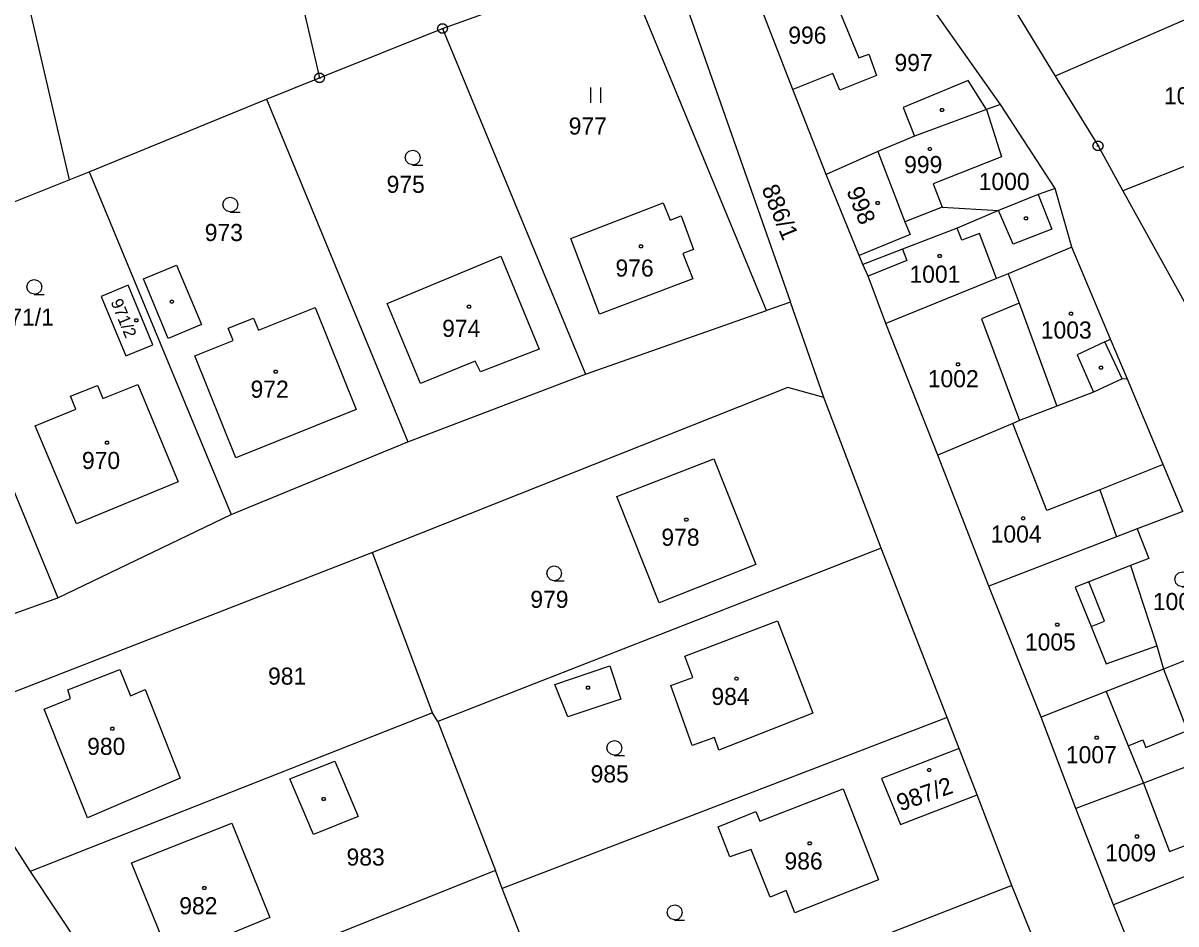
# Model space of a CAD drawing. Extents: x -609861 to -605046, y -1120287 to -1116307.
# Drawn here: x -607750.1 to -607635.6, y -1118647.5 to -1118558 of the extents above; entities that cross this region are included whole.
import ezdxf

# ---------------------------------------------------------------- set-up
doc = ezdxf.new("R2010")
doc.units = 0
for name, color, linetype in [('Vrstva 1', 7, 'Continuous'), ('Vrstva 2', 7, 'Continuous'), ('Vrstva 3', 7, 'Continuous'), ('Vrstva 4', 7, 'Continuous'), ('Vrstva 5', 7, 'Continuous'), ('Vrstva 8', 7, 'Continuous')]:
    doc.layers.add(name, color=color, linetype=linetype)

msp = doc.modelspace()

# ---------------------------------------------------------------- linework, layer by layer
at = {"layer": 'Vrstva 1'}
for p, q in [((-607730.23, -1118522.38), (-607720.65, -1118563.48)), ((-607755.47, -1118530.89), (-607745.51, -1118573.59)), ((-607660.15, -1118542.68), (-607647.55, -1118563.29)), ((-607653, -1118566.11), (-607664.28, -1118550.12)), ((-607708.42, -1118558.58), (-607690.47, -1118552.09)), ((-607676.23, -1118586.6), (-607690.47, -1118552.09)), ((-607670.62, -1118552.83), (-607667.08, -1118561.49)), ((-607673.61, -1118564.63), (-607677.14, -1118555.55)), ((-607628.52, -1118555.04), (-607647.55, -1118563.29)), ((-607720.65, -1118563.48), (-607708.42, -1118558.58)), ((-607708.42, -1118558.58), (-607694.23, -1118592.93)), ((-607667.08, -1118561.49), (-607666.06, -1118561.12)), ((-607666.06, -1118561.12), (-607665.3, -1118563.25)), ((-607725.9, -1118565.58), (-607720.65, -1118563.48)), ((-607669.65, -1118563.04), (-607673.61, -1118564.63)), ((-607668.94, -1118564.69), (-607669.65, -1118563.04)), ((-607665.3, -1118563.25), (-607668.94, -1118564.69)), ((-607647.55, -1118563.29), (-607643.3, -1118570.24)), ((-607670.31, -1118573.08), (-607673.61, -1118564.63)), ((-607743.54, -1118572.8), (-607725.9, -1118565.58)), ((-607725.9, -1118565.58), (-607711.86, -1118599.65)), ((-607617.91, -1118565.65), (-607640.84, -1118574.69)), ((-607654.38, -1118566.61), (-607661.54, -1118569.27)), ((-607653, -1118566.11), (-607654.38, -1118566.61)), ((-607654.38, -1118566.61), (-607652.88, -1118571.31)), ((-607647.55, -1118574.46), (-607653, -1118566.11)), ((-607661.54, -1118569.27), (-607665.19, -1118570.8)), ((-607643.3, -1118570.24), (-607640.84, -1118574.69)), ((-607665.19, -1118570.8), (-607670.31, -1118573.08)), ((-607665.19, -1118570.8), (-607662.49, -1118577.77)), ((-607652.88, -1118571.31), (-607659.69, -1118573.99)), ((-607745.51, -1118573.59), (-607743.54, -1118572.8)), ((-607743.54, -1118572.8), (-607729.42, -1118606.85)), ((-607761.2, -1118579.87), (-607745.51, -1118573.59)), ((-607667.04, -1118581.14), (-607670.31, -1118573.08)), ((-607659.69, -1118573.99), (-607658.78, -1118576.32)), ((-607649.25, -1118575.07), (-607653.19, -1118576.66)), ((-607647.55, -1118574.46), (-607649.25, -1118575.07)), ((-607645.91, -1118580.29), (-607647.55, -1118574.46)), ((-607640.84, -1118574.69), (-607634.25, -1118586.59)), ((-607695.68, -1118579.42), (-607686.49, -1118575.9)), ((-607686.49, -1118575.9), (-607685.82, -1118577.61)), ((-607658.78, -1118576.32), (-607653.19, -1118576.66)), ((-607685.82, -1118577.61), (-607684.73, -1118577.18)), ((-607684.73, -1118577.18), (-607683.49, -1118580.52)), ((-607653.19, -1118576.66), (-607657.29, -1118578.41)), ((-607657.29, -1118578.41), (-607662.74, -1118580.49)), ((-607662.49, -1118577.77), (-607661.97, -1118579.03)), ((-607692.84, -1118586.96), (-607695.68, -1118579.42)), ((-607661.97, -1118579.03), (-607667.04, -1118581.14)), ((-607761.2, -1118579.87), (-607746.66, -1118615.13)), ((-607683.49, -1118580.52), (-607684.54, -1118580.92)), ((-607684.54, -1118580.92), (-607683.55, -1118583.45)), ((-607662.74, -1118580.49), (-607666.66, -1118582.03)), ((-607645.91, -1118580.29), (-607652.23, -1118582.94)), ((-607642.06, -1118589.44), (-607645.91, -1118580.29)), ((-607713.94, -1118585.88), (-607702.62, -1118581.18)), ((-607702.62, -1118581.18), (-607698.84, -1118590.43)), ((-607666.66, -1118582.03), (-607667.04, -1118581.14)), ((-607666.15, -1118583.18), (-607666.66, -1118582.03)), ((-607664.37, -1118587.87), (-607666.15, -1118583.18)), ((-607652.23, -1118582.94), (-607653.4, -1118583.4)), ((-607652.23, -1118582.94), (-607651.15, -1118585.87)), ((-607739.67, -1118584.09), (-607742.35, -1118585.2)), ((-607737.22, -1118590), (-607739.67, -1118584.09)), ((-607683.55, -1118583.45), (-607692.84, -1118586.96)), ((-607653.4, -1118583.4), (-607664.37, -1118587.87)), ((-607742.35, -1118585.2), (-607739.9, -1118591.11)), ((-607726.72, -1118588.56), (-607721.08, -1118586.29)), ((-607721.08, -1118586.29), (-607717, -1118596.43)), ((-607710.62, -1118593.83), (-607713.94, -1118585.88)), ((-607694.23, -1118592.93), (-607676.23, -1118586.6)), ((-607673.85, -1118585.76), (-607676.23, -1118586.6)), ((-607670.53, -1118595.23), (-607673.85, -1118585.76)), ((-607651.15, -1118585.87), (-607647.4, -1118596.09)), ((-607729.72, -1118588.35), (-607727.21, -1118587.35)), ((-607727.21, -1118587.35), (-607726.72, -1118588.56)), ((-607729.24, -1118589.56), (-607729.72, -1118588.35)), ((-607659.21, -1118600.97), (-607664.37, -1118587.87)), ((-607739.9, -1118591.11), (-607737.22, -1118590)), ((-607733.03, -1118591.08), (-607729.24, -1118589.56)), ((-607640.38, -1118593.42), (-607642.06, -1118589.44)), ((-607728.97, -1118601.24), (-607733.03, -1118591.08)), ((-607698.84, -1118590.43), (-607704.66, -1118592.69)), ((-607705.19, -1118591.63), (-607710.62, -1118593.83)), ((-607704.66, -1118592.69), (-607705.19, -1118591.63)), ((-607711.86, -1118599.65), (-607694.23, -1118592.93)), ((-607640.91, -1118593.38), (-607643.76, -1118594.69)), ((-607640.38, -1118593.42), (-607640.91, -1118593.38)), ((-607636.82, -1118601.91), (-607640.38, -1118593.42)), ((-607745.38, -1118595.11), (-607742.71, -1118594.03)), ((-607742.71, -1118594.03), (-607742.18, -1118595.33)), ((-607742.18, -1118595.33), (-607738.71, -1118593.93)), ((-607738.71, -1118593.93), (-607734.68, -1118603.61)), ((-607674.13, -1118594.25), (-607715.38, -1118610.65)), ((-607670.53, -1118595.23), (-607674.13, -1118594.25)), ((-607643.76, -1118594.69), (-607647.4, -1118596.09)), ((-607744.85, -1118596.41), (-607745.38, -1118595.11)), ((-607664.84, -1118610.21), (-607670.53, -1118595.23)), ((-607748.89, -1118598.04), (-607744.85, -1118596.41)), ((-607717, -1118596.43), (-607728.97, -1118601.24)), ((-607647.4, -1118596.09), (-607651.09, -1118597.52)), ((-607744.78, -1118607.78), (-607748.89, -1118598.04)), ((-607651.78, -1118597.81), (-607659.21, -1118600.97)), ((-607651.09, -1118597.52), (-607651.78, -1118597.81)), ((-607729.42, -1118606.85), (-607711.86, -1118599.65)), ((-607691.11, -1118605.06), (-607681.46, -1118601.32)), ((-607681.46, -1118601.32), (-607677.31, -1118611.84)), ((-607654.15, -1118613.99), (-607659.21, -1118600.97)), ((-607634.87, -1118606.57), (-607636.82, -1118601.91)), ((-607734.68, -1118603.61), (-607744.78, -1118607.78)), ((-607686.91, -1118615.63), (-607691.11, -1118605.06)), ((-607746.66, -1118615.13), (-607729.42, -1118606.85)), ((-607634.87, -1118606.57), (-607639.42, -1118608.28)), ((-607639.42, -1118608.28), (-607641.47, -1118609.07)), ((-607639.42, -1118608.28), (-607638.26, -1118611.23)), ((-607641.47, -1118609.07), (-607654.15, -1118613.99)), ((-607715.38, -1118610.65), (-607756.88, -1118626.8)), ((-607709.43, -1118626.56), (-607715.38, -1118610.65)), ((-607664.84, -1118610.21), (-607708.9, -1118627.42)), ((-607658.28, -1118627.02), (-607664.84, -1118610.21)), ((-607677.31, -1118611.84), (-607686.91, -1118615.63)), ((-607638.26, -1118611.23), (-607640.09, -1118611.94)), ((-607640.09, -1118611.94), (-607637.47, -1118619.92)), ((-607648.96, -1118627.01), (-607654.15, -1118613.99)), ((-607764.5, -1118621.59), (-607746.66, -1118615.13)), ((-607684.34, -1118620.95), (-607675.16, -1118617.44)), ((-607675.16, -1118617.44), (-607671.62, -1118626.62)), ((-607637.47, -1118619.92), (-607636.78, -1118622.22)), ((-607629.89, -1118619.47), (-607636.78, -1118622.22)), ((-607683.57, -1118623.05), (-607684.34, -1118620.95)), ((-607745.64, -1118624.28), (-607740.49, -1118622.28)), ((-607740.49, -1118622.28), (-607739.43, -1118624.87)), ((-607685.76, -1118623.84), (-607683.57, -1118623.05)), ((-607636.78, -1118622.22), (-607642.48, -1118624.46)), ((-607636.78, -1118622.22), (-607633.22, -1118631.43)), ((-607745.39, -1118625.15), (-607745.64, -1118624.28)), ((-607739.43, -1118624.87), (-607737.97, -1118624.25)), ((-607737.97, -1118624.25), (-607734.5, -1118633.08)), ((-607683.61, -1118629.82), (-607685.76, -1118623.84)), ((-607642.48, -1118624.46), (-607648.96, -1118627.01)), ((-607748, -1118626.22), (-607745.39, -1118625.15)), ((-607709.43, -1118626.56), (-607749.41, -1118642.33)), ((-607743.71, -1118636.99), (-607748, -1118626.22)), ((-607708.9, -1118627.42), (-607709.43, -1118626.56)), ((-607671.62, -1118626.62), (-607680.96, -1118630.27)), ((-607708.9, -1118627.42), (-607703.18, -1118642.25)), ((-607658.28, -1118627.02), (-607702.49, -1118644.04)), ((-607657.09, -1118630.11), (-607658.28, -1118627.02)), ((-607645.5, -1118636.07), (-607648.96, -1118627.01)), ((-607681.41, -1118629.02), (-607683.61, -1118629.82)), ((-607680.96, -1118630.27), (-607681.41, -1118629.02)), ((-607757.51, -1118629.71), (-607749.41, -1118642.33)), ((-607655.32, -1118634.73), (-607657.09, -1118630.11)), ((-607633.42, -1118631.51), (-607638.79, -1118633.56)), ((-607734.5, -1118633.08), (-607743.71, -1118636.99)), ((-607638.79, -1118633.56), (-607645.5, -1118636.07)), ((-607676.91, -1118637.34), (-607668.63, -1118634.11)), ((-607668.63, -1118634.11), (-607665.1, -1118643.17)), ((-607651.86, -1118643.74), (-607655.32, -1118634.73)), ((-607681.03, -1118637.89), (-607677.29, -1118636.36)), ((-607677.29, -1118636.36), (-607676.91, -1118637.34)), ((-607641.77, -1118645.64), (-607645.5, -1118636.07)), ((-607739.33, -1118641.48), (-607729.35, -1118637.54)), ((-607729.35, -1118637.54), (-607725.57, -1118646.92)), ((-607679.89, -1118640.87), (-607681.03, -1118637.89)), ((-607622.91, -1118638.17), (-607641.77, -1118645.64)), ((-607677.76, -1118640.14), (-607679.89, -1118640.87)), ((-607675.88, -1118644.9), (-607677.76, -1118640.14)), ((-607734.81, -1118652.62), (-607739.33, -1118641.48)), ((-607749.41, -1118642.33), (-607739.77, -1118656.82)), ((-607703.18, -1118642.25), (-607739.77, -1118656.82)), ((-607702.49, -1118644.04), (-607703.18, -1118642.25)), ((-607651.86, -1118643.74), (-607695.92, -1118660.88)), ((-607665.1, -1118643.17), (-607673.41, -1118646.44)), ((-607645.11, -1118660.42), (-607651.86, -1118643.74)), ((-607696.63, -1118659.04), (-607702.49, -1118644.04)), ((-607674.27, -1118644.21), (-607675.88, -1118644.9)), ((-607673.41, -1118646.44), (-607674.27, -1118644.21)), ((-607635.54, -1118661.21), (-607641.77, -1118645.64)), ((-607725.57, -1118646.92), (-607729.37, -1118648.45))]:
    msp.add_line(p, q, dxfattribs=at)
msp.add_lwpolyline([(-607657.09, -1118630.11), (-607664.8, -1118633.11), (-607662.93, -1118637.68), (-607655.32, -1118634.73)], dxfattribs=at)
at = {"layer": 'Vrstva 3'}
for p, q in [((-607693.71, -1118564.44), (-607693.71, -1118565.94)), ((-607692.71, -1118565.94), (-607692.71, -1118564.44))]:
    msp.add_line(p, q, dxfattribs=at)
for points in [[(-607711.38, -1118572.13), (-607711.76, -1118572.03), (-607712.03, -1118571.76), (-607712.13, -1118571.39), (-607712.03, -1118571.02), (-607711.76, -1118570.75), (-607711.39, -1118570.65), (-607711.02, -1118570.75), (-607710.75, -1118571.02), (-607710.65, -1118571.4), (-607710.75, -1118571.78), (-607711.02, -1118572.05), (-607711.4, -1118572.15), (-607710.4, -1118572.15)], [(-607729.51, -1118576.8), (-607729.89, -1118576.7), (-607730.16, -1118576.43), (-607730.26, -1118576.06), (-607730.16, -1118575.69), (-607729.89, -1118575.42), (-607729.52, -1118575.32), (-607729.15, -1118575.42), (-607728.88, -1118575.69), (-607728.78, -1118576.07), (-607728.88, -1118576.45), (-607729.15, -1118576.72), (-607729.53, -1118576.82), (-607728.53, -1118576.82)], [(-607748.98, -1118584.98), (-607749.36, -1118584.88), (-607749.63, -1118584.61), (-607749.73, -1118584.24), (-607749.63, -1118583.87), (-607749.36, -1118583.6), (-607748.99, -1118583.5), (-607748.62, -1118583.6), (-607748.35, -1118583.87), (-607748.25, -1118584.25), (-607748.35, -1118584.63), (-607748.62, -1118584.9), (-607749, -1118585), (-607748, -1118585)], [(-607697.33, -1118613.44), (-607697.71, -1118613.34), (-607697.98, -1118613.07), (-607698.08, -1118612.7), (-607697.98, -1118612.33), (-607697.71, -1118612.06), (-607697.34, -1118611.96), (-607696.97, -1118612.06), (-607696.7, -1118612.33), (-607696.6, -1118612.71), (-607696.7, -1118613.09), (-607696.97, -1118613.36), (-607697.35, -1118613.46), (-607696.35, -1118613.46)], [(-607634.91, -1118614.04), (-607635.29, -1118613.94), (-607635.56, -1118613.67), (-607635.66, -1118613.3), (-607635.56, -1118612.93), (-607635.29, -1118612.66), (-607634.92, -1118612.56), (-607634.55, -1118612.66), (-607634.28, -1118612.93), (-607634.18, -1118613.31), (-607634.28, -1118613.69), (-607634.55, -1118613.96), (-607634.93, -1118614.06), (-607633.93, -1118614.06)], [(-607691.34, -1118630.79), (-607691.72, -1118630.69), (-607691.99, -1118630.42), (-607692.09, -1118630.05), (-607691.99, -1118629.68), (-607691.72, -1118629.41), (-607691.35, -1118629.31), (-607690.98, -1118629.41), (-607690.71, -1118629.68), (-607690.61, -1118630.06), (-607690.71, -1118630.44), (-607690.98, -1118630.71), (-607691.36, -1118630.81), (-607690.36, -1118630.81)], [(-607685.35, -1118647.14), (-607685.73, -1118647.04), (-607686, -1118646.77), (-607686.1, -1118646.4), (-607686, -1118646.03), (-607685.73, -1118645.76), (-607685.36, -1118645.66), (-607684.99, -1118645.76), (-607684.72, -1118646.03), (-607684.62, -1118646.41), (-607684.72, -1118646.79), (-607684.99, -1118647.06), (-607685.37, -1118647.16), (-607684.37, -1118647.16)]]:
    msp.add_lwpolyline(points, dxfattribs=at)
for points in [[(-607645.91, -1118586.75), (-607645.82, -1118586.9), (-607645.91, -1118587.05), (-607646.09, -1118587.05), (-607646.18, -1118586.9), (-607646.09, -1118586.75)], [(-607642.93, -1118592.11), (-607642.84, -1118592.26), (-607642.93, -1118592.41), (-607643.11, -1118592.41), (-607643.2, -1118592.26), (-607643.11, -1118592.11)]]:
    msp.add_lwpolyline(points, close=True, dxfattribs=at)
at = {"layer": 'Vrstva 4'}
for p, q in [((-607684.75, -1118554.69), (-607673.85, -1118585.76)), ((-607656.19, -1118563.74), (-607662.66, -1118566.42)), ((-607654.38, -1118566.61), (-607656.19, -1118563.74)), ((-607662.66, -1118566.42), (-607661.54, -1118569.27)), ((-607649.25, -1118575.07), (-607647.9, -1118578.51)), ((-607658.78, -1118576.32), (-607662.49, -1118577.77)), ((-607651.72, -1118580), (-607653.19, -1118576.66)), ((-607656.82, -1118579.61), (-607657.29, -1118578.41)), ((-607647.9, -1118578.51), (-607651.72, -1118580)), ((-607655.08, -1118578.95), (-607656.82, -1118579.61)), ((-607653.4, -1118583.4), (-607655.08, -1118578.95)), ((-607662.74, -1118580.49), (-607662.3, -1118581.62)), ((-607738.15, -1118583.45), (-607734.85, -1118582.07)), ((-607734.85, -1118582.07), (-607732.38, -1118587.99)), ((-607662.3, -1118581.62), (-607666.15, -1118583.18)), ((-607735.67, -1118589.37), (-607738.15, -1118583.45)), ((-607651.15, -1118585.87), (-607654.89, -1118587.43)), ((-607654.89, -1118587.43), (-607651.09, -1118597.52)), ((-607732.38, -1118587.99), (-607735.67, -1118589.37)), ((-607642.63, -1118589.7), (-607645.39, -1118590.98)), ((-607642.63, -1118589.7), (-607642.06, -1118589.44)), ((-607640.91, -1118593.38), (-607642.63, -1118589.7)), ((-607645.39, -1118590.98), (-607643.76, -1118594.69)), ((-607648.39, -1118606.48), (-607651.78, -1118597.81)), ((-607636.82, -1118601.91), (-607643.12, -1118604.4)), ((-607643.12, -1118604.4), (-607648.39, -1118606.48)), ((-607643.12, -1118604.4), (-607641.47, -1118609.07)), ((-607640.09, -1118611.94), (-607644.2, -1118613.55)), ((-607644.2, -1118613.55), (-607645.57, -1118614.08)), ((-607645.57, -1118614.08), (-607643.99, -1118618)), ((-607643.99, -1118618), (-607642.5, -1118621.7)), ((-607642.5, -1118621.7), (-607637.47, -1118619.92)), ((-607697.27, -1118623.77), (-607691.82, -1118621.89)), ((-607691.82, -1118621.89), (-607690.7, -1118625.2)), ((-607695.97, -1118626.98), (-607697.27, -1118623.77)), ((-607642.48, -1118624.46), (-607640.3, -1118629.84)), ((-607690.7, -1118625.2), (-607695.97, -1118626.98)), ((-607638.54, -1118630), (-607634.66, -1118628.43)), ((-607640.3, -1118629.84), (-607638.84, -1118629.26)), ((-607640.3, -1118629.84), (-607638.79, -1118633.56)), ((-607638.84, -1118629.26), (-607638.54, -1118630)), ((-607723.59, -1118633.14), (-607719.12, -1118631.39)), ((-607719.12, -1118631.39), (-607716.81, -1118636.88)), ((-607721.24, -1118638.67), (-607723.59, -1118633.14)), ((-607638.79, -1118633.56), (-607636.19, -1118640.36)), ((-607716.81, -1118636.88), (-607721.24, -1118638.67)), ((-607636.19, -1118640.36), (-607630.6, -1118638.2))]:
    msp.add_line(p, q, dxfattribs=at)
msp.add_lwpolyline([(-607643.99, -1118618), (-607642.65, -1118617.46), (-607644.2, -1118613.55)], dxfattribs=at)
at = {"layer": 'Vrstva 5'}
for points in [[(-607658.7, -1118566.51), (-607658.61, -1118566.66), (-607658.7, -1118566.81), (-607658.88, -1118566.81), (-607658.97, -1118566.66), (-607658.88, -1118566.51)], [(-607659.92, -1118570.38), (-607659.83, -1118570.53), (-607659.92, -1118570.68), (-607660.1, -1118570.68), (-607660.19, -1118570.53), (-607660.1, -1118570.38)], [(-607665.1, -1118575.76), (-607665.01, -1118575.91), (-607665.1, -1118576.06), (-607665.28, -1118576.06), (-607665.37, -1118575.91), (-607665.28, -1118575.76)], [(-607650.38, -1118577.29), (-607650.29, -1118577.44), (-607650.38, -1118577.59), (-607650.56, -1118577.59), (-607650.65, -1118577.44), (-607650.56, -1118577.29)], [(-607688.61, -1118580.08), (-607688.52, -1118580.23), (-607688.61, -1118580.38), (-607688.79, -1118580.38), (-607688.88, -1118580.23), (-607688.79, -1118580.08)], [(-607658.94, -1118581.04), (-607658.85, -1118581.19), (-607658.94, -1118581.34), (-607659.12, -1118581.34), (-607659.21, -1118581.19), (-607659.12, -1118581.04)], [(-607735.23, -1118585.55), (-607735.14, -1118585.7), (-607735.23, -1118585.85), (-607735.41, -1118585.85), (-607735.5, -1118585.7), (-607735.41, -1118585.55)], [(-607705.72, -1118586.07), (-607705.63, -1118586.22), (-607705.72, -1118586.37), (-607705.9, -1118586.37), (-607705.99, -1118586.22), (-607705.9, -1118586.07)], [(-607738.76, -1118587.41), (-607738.67, -1118587.56), (-607738.76, -1118587.71), (-607738.94, -1118587.71), (-607739.03, -1118587.56), (-607738.94, -1118587.41)], [(-607657.12, -1118591.8), (-607657.03, -1118591.95), (-607657.12, -1118592.1), (-607657.3, -1118592.1), (-607657.39, -1118591.95), (-607657.3, -1118591.8)], [(-607724.92, -1118592.51), (-607724.83, -1118592.66), (-607724.92, -1118592.81), (-607725.1, -1118592.81), (-607725.19, -1118592.66), (-607725.1, -1118592.51)], [(-607741.67, -1118599.59), (-607741.58, -1118599.74), (-607741.67, -1118599.89), (-607741.85, -1118599.89), (-607741.94, -1118599.74), (-607741.85, -1118599.59)], [(-607684.1, -1118607.22), (-607684.01, -1118607.37), (-607684.1, -1118607.52), (-607684.28, -1118607.52), (-607684.37, -1118607.37), (-607684.28, -1118607.22)], [(-607650.65, -1118607.08), (-607650.56, -1118607.23), (-607650.65, -1118607.38), (-607650.83, -1118607.38), (-607650.92, -1118607.23), (-607650.83, -1118607.08)], [(-607647.25, -1118617.65), (-607647.16, -1118617.8), (-607647.25, -1118617.95), (-607647.43, -1118617.95), (-607647.52, -1118617.8), (-607647.43, -1118617.65)], [(-607679.13, -1118623.04), (-607679.04, -1118623.19), (-607679.13, -1118623.34), (-607679.31, -1118623.34), (-607679.4, -1118623.19), (-607679.31, -1118623.04)], [(-607693.88, -1118623.93), (-607693.79, -1118624.08), (-607693.88, -1118624.23), (-607694.06, -1118624.23), (-607694.15, -1118624.08), (-607694.06, -1118623.93)], [(-607741.15, -1118628), (-607741.06, -1118628.15), (-607741.15, -1118628.3), (-607741.33, -1118628.3), (-607741.42, -1118628.15), (-607741.33, -1118628)], [(-607643.35, -1118628.9), (-607643.26, -1118629.05), (-607643.35, -1118629.2), (-607643.53, -1118629.2), (-607643.62, -1118629.05), (-607643.53, -1118628.9)], [(-607659.99, -1118632.1), (-607659.9, -1118632.25), (-607659.99, -1118632.4), (-607660.17, -1118632.4), (-607660.26, -1118632.25), (-607660.17, -1118632.1)], [(-607720.15, -1118634.97), (-607720.06, -1118635.12), (-607720.15, -1118635.27), (-607720.33, -1118635.27), (-607720.42, -1118635.12), (-607720.33, -1118634.97)], [(-607671.87, -1118639.39), (-607671.78, -1118639.54), (-607671.87, -1118639.69), (-607672.05, -1118639.69), (-607672.14, -1118639.54), (-607672.05, -1118639.39)], [(-607639.33, -1118638.71), (-607639.24, -1118638.86), (-607639.33, -1118639.01), (-607639.51, -1118639.01), (-607639.6, -1118638.86), (-607639.51, -1118638.71)], [(-607732, -1118643.84), (-607731.91, -1118643.99), (-607732, -1118644.14), (-607732.18, -1118644.14), (-607732.27, -1118643.99), (-607732.18, -1118643.84)]]:
    msp.add_lwpolyline(points, close=True, dxfattribs=at)
at = {"layer": 'Vrstva 8'}
for p, q in [((-607708.54, -1118558.58), (-607708.3, -1118558.58)), ((-607720.77, -1118563.48), (-607720.53, -1118563.48)), ((-607643.42, -1118570.24), (-607643.18, -1118570.24))]:
    msp.add_line(p, q, dxfattribs=at)
for points in [[(-607708.27, -1118558.1), (-607708.02, -1118558.28), (-607707.92, -1118558.57), (-607708.02, -1118558.86), (-607708.27, -1118559.04), (-607708.58, -1118559.04), (-607708.83, -1118558.86), (-607708.93, -1118558.57), (-607708.83, -1118558.28), (-607708.58, -1118558.1)], [(-607720.5, -1118563), (-607720.25, -1118563.18), (-607720.15, -1118563.47), (-607720.25, -1118563.76), (-607720.5, -1118563.94), (-607720.81, -1118563.94), (-607721.06, -1118563.76), (-607721.16, -1118563.47), (-607721.06, -1118563.18), (-607720.81, -1118563)], [(-607643.15, -1118569.76), (-607642.9, -1118569.94), (-607642.8, -1118570.23), (-607642.9, -1118570.52), (-607643.15, -1118570.7), (-607643.46, -1118570.7), (-607643.71, -1118570.52), (-607643.81, -1118570.23), (-607643.71, -1118569.94), (-607643.46, -1118569.76)]]:
    msp.add_lwpolyline(points, close=True, dxfattribs=at)

# ---------------------------------------------------------------- texts
at = {"layer": 'Vrstva 2'}
for s, p in [('996', (-607674.073, -1118560.08)), ('997', (-607663.523, -1118562.8)), ('1020/8', (-607636.747, -1118566.1)), ('977', (-607695.893, -1118569.11)), ('999', (-607662.563, -1118572.94)), ('1000', (-607655.157, -1118574.62)), ('975', (-607713.983, -1118574.9)), ('973', (-607732.053, -1118579.69)), ('976', (-607691.243, -1118583.22)), ('1001', (-607662.037, -1118583.83)), ('971/1', (-607752.733, -1118588.1)), ('974', (-607708.463, -1118589.21)), ('1003', (-607648.987, -1118589.38)), ('972', (-607727.503, -1118595.26)), ('1002', (-607660.217, -1118594.22)), ('970', (-607744.253, -1118602.34)), ('978', (-607686.683, -1118609.97)), ('1004', (-607653.967, -1118609.65)), ('979', (-607699.703, -1118616.14)), ('1006', (-607637.857, -1118616.36)), ('1005', (-607650.567, -1118620.38)), ('981', (-607725.763, -1118623.77)), ('984', (-607681.713, -1118625.79)), ('980', (-607743.733, -1118630.75)), ('1007', (-607646.497, -1118631.58)), ('985', (-607693.713, -1118633.49)), ('983', (-607717.963, -1118641.75)), ('986', (-607674.453, -1118642.14)), ('1009', (-607642.597, -1118641.33)), ('982', (-607734.583, -1118646.59))]:
    msp.add_text(s, height=1.7, dxfattribs=at).set_placement(p)
for s, height, rotation, p in [('886/1', 1.7, 292.49496, (-607676.759, -1118574.489)), ('998', 1.7, 291.57822, (-607668.323, -1118574.681)), ('971/2', 1.2, 292.49496, (-607741.426, -1118585.725)), ('987/2', 1.7, 19.42327, (-607662.945, -1118636.382))]:
    msp.add_text(s, height=height, rotation=rotation, dxfattribs=at).set_placement(p)

doc.saveas('drawing.dxf')
